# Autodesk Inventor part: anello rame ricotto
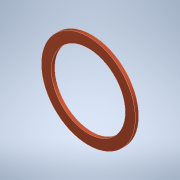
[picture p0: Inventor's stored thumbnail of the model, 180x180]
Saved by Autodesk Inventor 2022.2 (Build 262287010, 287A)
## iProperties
Created: 2022-03
Part Number: anello rame ricotto
Material: Rame
Document SubType Name: Modeling
Designer: 18619647
Density: 8.94 g/cm^3
Appearance: Rame - Satinato
Author: 18619647
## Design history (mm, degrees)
sketch "Schizzo1"
  geometry: C1 r 11 at (0, 0); C2 r 14 at (0, 0); 1 further point
  constraints: 2 centre point, 2 coincident
  dimensions: "d0" = 22 diameter of C1; "d1" = 28 diameter of C2
extrude "Estrusione1" new body sketch "Schizzo1" distance "d2" = 1; taper "d3" = 0 deg
node "Solido1"
